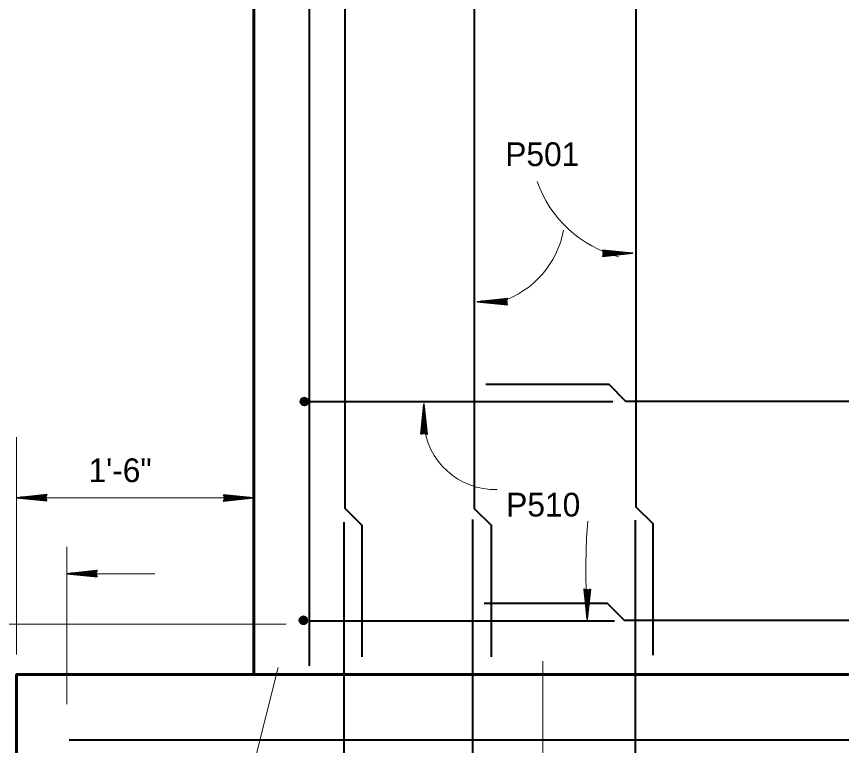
# Model space of a CAD drawing. Extents: x 3.64 to 6.84, y -0.8 to 1.19.
# Drawn here: x 3.9444 to 4.2342, y -0.0837 to 0.1724 of the extents above; entities that cross this region are included whole.
import ezdxf

# ---------------------------------------------------------------- set-up
doc = ezdxf.new("R2010")
doc.units = 0
doc.header["$LTSCALE"] = 0.0033
doc.linetypes.add('DOT_DASHED', pattern=[7.7, 5, -1.2, 0.3, -1.2])
doc.linetypes.add('MEDIUM_DASHED', pattern=[4.5, 3, -1.5])
doc.layers.add('1', color=7, linetype='Continuous', lineweight=40)
doc.layers.add('5', color=7, linetype='MEDIUM_DASHED', lineweight=13)

msp = doc.modelspace()

# ---------------------------------------------------------------- linework, layer by layer
at = {"layer": '1'}
for p, q in [((4.04725, 0.2535), (4.04725, -0.055667)), ((4.044333, 0.036417), (4.044417, 0.037917)), ((4.0445, 0.036417), (4.044583, 0.037917)), ((4.044583, 0.036417), (4.044667, 0.037917)), ((4.046583, 0.0375), (4.044583, 0.037833)), ((4.046667, 0.03775), (4.044667, 0.038083)), ((4.046583, 0.037667), (4.044667, 0.038)), ((4.044667, 0.036417), (4.04475, 0.037917)), ((4.046583, 0.037583), (4.044667, 0.037917)), ((4.04475, 0.036417), (4.044833, 0.037917)), ((4.044833, 0.036417), (4.044917, 0.037917)), ((4.044917, 0.036417), (4.045, 0.037917)), ((4.045, 0.036417), (4.045083, 0.037917)), ((4.045, 0.036417), (4.045083, 0.037917)), ((4.045083, 0.036417), (4.04525, 0.037917)), ((4.04525, 0.036417), (4.045417, 0.037917)), ((4.045417, 0.036333), (4.0455, 0.037833)), ((4.0455, 0.036333), (4.045583, 0.037833)), ((4.045583, 0.036333), (4.045667, 0.037833)), ((4.045667, 0.036333), (4.04575, 0.037833)), ((4.04575, 0.036333), (4.045833, 0.037833)), ((4.045833, 0.036333), (4.045917, 0.037833)), ((4.045917, 0.036333), (4.046, 0.037833)), ((4.046083, 0.036333), (4.046167, 0.037833)), ((4.046167, 0.036333), (4.04625, 0.037833)), ((4.04625, 0.036333), (4.046333, 0.037833)), ((4.046333, 0.036333), (4.046417, 0.037833)), ((4.046417, 0.036333), (4.0465, 0.037833)), ((4.046417, 0.036583), (4.044417, 0.037)), ((4.046417, 0.0365), (4.044417, 0.036917)), ((4.046417, 0.036417), (4.044417, 0.03675)), ((4.046417, 0.036333), (4.044417, 0.036667)), ((4.046333, 0.036167), (4.044417, 0.0365)), ((4.0465, 0.036917), (4.0445, 0.037333)), ((4.0465, 0.036833), (4.0445, 0.037167)), ((4.046417, 0.03675), (4.0445, 0.037083)), ((4.046583, 0.03725), (4.044583, 0.037667)), ((4.0465, 0.037083), (4.044583, 0.0375)), ((4.0465, 0.037), (4.044583, 0.037417)), ((4.046583, 0.037167), (4.153917, 0.037167)), ((4.059417, -0.00525), (4.059417, -0.117083)), ((4.104583, -0.00425), (4.104583, -0.11725)), ((4.161667, -0.0045), (4.161667, -0.1175)), ((4.044, -0.040417), (4.044083, -0.038917)), ((4.046083, -0.04025), (4.044083, -0.039833)), ((4.046083, -0.040333), (4.044083, -0.039917)), ((4.046083, -0.040417), (4.044083, -0.040083)), ((4.046083, -0.0405), (4.044083, -0.040167)), ((4.046, -0.040667), (4.044083, -0.040333)), ((4.044167, -0.040417), (4.04425, -0.038917)), ((4.046167, -0.039917), (4.044167, -0.0395)), ((4.046167, -0.04), (4.044167, -0.039667)), ((4.046083, -0.040083), (4.044167, -0.03975)), ((4.04425, -0.040417), (4.044333, -0.038917)), ((4.04625, -0.039333), (4.04425, -0.039)), ((4.04625, -0.039583), (4.04425, -0.039167)), ((4.046167, -0.03975), (4.04425, -0.039333)), ((4.046167, -0.039833), (4.04425, -0.039417)), ((4.046333, -0.039083), (4.044333, -0.03875)), ((4.04625, -0.039167), (4.044333, -0.038833)), ((4.044333, -0.040417), (4.044417, -0.038917)), ((4.04625, -0.03925), (4.044333, -0.038917)), ((4.044417, -0.040417), (4.0445, -0.038917)), ((4.0445, -0.040417), (4.044583, -0.038917)), ((4.044583, -0.040417), (4.044667, -0.038917)), ((4.044667, -0.040417), (4.04475, -0.038917)), ((4.044667, -0.040417), (4.04475, -0.038917)), ((4.04475, -0.040417), (4.044917, -0.038917)), ((4.044917, -0.040417), (4.045083, -0.038917)), ((4.045083, -0.0405), (4.045167, -0.039)), ((4.045167, -0.0405), (4.04525, -0.039)), ((4.04525, -0.0405), (4.045333, -0.039)), ((4.045333, -0.0405), (4.045417, -0.039)), ((4.045417, -0.0405), (4.0455, -0.039)), ((4.0455, -0.0405), (4.045583, -0.039)), ((4.045583, -0.0405), (4.045667, -0.039)), ((4.04575, -0.0405), (4.045833, -0.039)), ((4.045833, -0.0405), (4.045917, -0.039)), ((4.045917, -0.0405), (4.046, -0.039)), ((4.046, -0.0405), (4.046083, -0.039)), ((4.046083, -0.0405), (4.046167, -0.039)), ((4.047667, -0.039833), (4.1545, -0.039833))]:
    msp.add_line(p, q, dxfattribs=at)
at = {"layer": '1', "lineweight": 35}
for p, q in [((4.1505, 0.09025), (4.158333, 0.089333)), ((4.1505, 0.09025), (4.158333, 0.089333)), ((4.1505, 0.090167), (4.158333, 0.089333)), ((4.1505, 0.090083), (4.158333, 0.08925)), ((4.1505, 0.090083), (4.158333, 0.089083)), ((4.15025, 0.08925), (4.160833, 0.08925)), ((4.150417, 0.088583), (4.15775, 0.089333)), ((4.1505, 0.088417), (4.157833, 0.08925)), ((4.1505, 0.088333), (4.157833, 0.089083)), ((4.1505, 0.088167), (4.157833, 0.089)), ((4.116583, 0.07325), (4.10925, 0.072417)), ((4.116583, 0.073083), (4.10925, 0.072333)), ((4.116583, 0.073), (4.10925, 0.072167)), ((4.116667, 0.072833), (4.109333, 0.072083)), ((4.116833, 0.072167), (4.10625, 0.072167)), ((4.116583, 0.071333), (4.10875, 0.072333)), ((4.116583, 0.071333), (4.10875, 0.072167)), ((4.116583, 0.071167), (4.10875, 0.072083)), ((4.116583, 0.071167), (4.10875, 0.072083)), ((4.116583, 0.07125), (4.10875, 0.072083)), ((4.0875, 0.025667), (4.0875, 0.03625)), ((4.0865, 0.025917), (4.087417, 0.03375)), ((4.0865, 0.025917), (4.087417, 0.03375)), ((4.086583, 0.025917), (4.087417, 0.03375)), ((4.086667, 0.025917), (4.0875, 0.03375)), ((4.086667, 0.025917), (4.087667, 0.03375)), ((4.088167, 0.025833), (4.087417, 0.033167)), ((4.088333, 0.025917), (4.0875, 0.03325)), ((4.088417, 0.025917), (4.087667, 0.03325)), ((4.088583, 0.025917), (4.08775, 0.03325)), ((3.955, 0.003333), (3.944417, 0.003333)), ((3.95475, 0.0025), (3.946917, 0.0035)), ((3.95475, 0.0025), (3.946917, 0.003333)), ((3.95475, 0.002333), (3.946917, 0.00325)), ((3.95475, 0.002333), (3.946917, 0.00325)), ((3.95475, 0.002417), (3.946917, 0.00325)), ((3.95475, 0.004417), (3.947417, 0.003583)), ((3.95475, 0.00425), (3.947417, 0.0035)), ((3.95475, 0.004167), (3.947417, 0.003333)), ((3.954833, 0.004), (3.9475, 0.00325)), ((4.017083, 0.003333), (4.027667, 0.003333)), ((4.01725, 0.002667), (4.024583, 0.003417)), ((4.017333, 0.004333), (4.025167, 0.003417)), ((4.017333, 0.004333), (4.025167, 0.003417)), ((4.017333, 0.00425), (4.025167, 0.003417)), ((4.017333, 0.004167), (4.025167, 0.003333)), ((4.017333, 0.004167), (4.025167, 0.003167)), ((4.017333, 0.0025), (4.024667, 0.003333)), ((4.017333, 0.002417), (4.024667, 0.003167)), ((4.017333, 0.00225), (4.024667, 0.003083)), ((3.972417, -0.024167), (3.964583, -0.023167)), ((3.972417, -0.02225), (3.965083, -0.023083)), ((3.972417, -0.022417), (3.965083, -0.023167)), ((3.972417, -0.0225), (3.965083, -0.023333)), ((3.9725, -0.022667), (3.965167, -0.023417)), ((3.972667, -0.023333), (3.962083, -0.023333)), ((3.972417, -0.024167), (3.964583, -0.023333)), ((3.972417, -0.024333), (3.964583, -0.023417)), ((3.972417, -0.024333), (3.964583, -0.023417)), ((3.972417, -0.02425), (3.964583, -0.023417)), ((4.14425, -0.028917), (4.145, -0.03625)), ((4.144917, -0.02875), (4.144917, -0.039333)), ((4.143833, -0.029), (4.144667, -0.036333)), ((4.144, -0.029), (4.14475, -0.036333)), ((4.144083, -0.029), (4.144917, -0.036333)), ((4.14575, -0.029), (4.14475, -0.036833)), ((4.14575, -0.029), (4.144917, -0.036833)), ((4.145917, -0.029), (4.145, -0.036833)), ((4.145917, -0.029), (4.145, -0.036833)), ((4.145833, -0.029), (4.145, -0.036833))]:
    msp.add_line(p, q, dxfattribs=at)
at = {"layer": '1', "lineweight": 13}
for p, q in [((3.944417, -0.05175), (3.944417, 0.024583)), ((3.944333, 0.003333), (4.02725, 0.003333)), ((3.962083, -0.069167), (3.962083, -0.013917)), ((3.972083, -0.023333), (3.992917, -0.023333)), ((4.039167, -0.041083), (3.863583, -0.041083))]:
    msp.add_line(p, q, dxfattribs=at)
at = {"layer": '1', "lineweight": 60}
for points in [[(3.944417, -0.142083), (3.944417, -0.05875), (4.02775, -0.05875), (4.02775, 0.274583)], [(4.02775, -0.05875), (4.270917, -0.05875), (4.611083, -0.05875)]]:
    msp.add_lwpolyline(points, dxfattribs=at)
at = {"layer": '1'}
for points in [[(4.05975, 0.253583), (4.05975, -0.000333), (4.065667, -0.00625), (4.065667, -0.0525)], [(4.111083, 0.253167), (4.111083, 0.213833), (4.105167, 0.207917), (4.105167, -0.000417), (4.111083, -0.006333), (4.111083, -0.052583)], [(4.167917, 0.252), (4.167917, 0.214417), (4.162, 0.2085), (4.162, 0.000167), (4.167917, -0.00575), (4.167917, -0.052)], [(4.51775, 0.043083), (4.474083, 0.043083), (4.468167, 0.037167), (4.253417, 0.037167), (4.1585, 0.037167), (4.152583, 0.043083), (4.10925, 0.043083)], [(4.046833, 0.037167), (4.04425, 0.036833), (4.046583, 0.036333), (4.04425, 0.037417), (4.046667, 0.037833), (4.044667, 0.038167), (4.044667, 0.036083), (4.045583, 0.038417), (4.045333, 0.035833), (4.046333, 0.038167), (4.046, 0.035833), (4.045167, 0.038417), (4.04675, 0.036667), (4.044333, 0.0365), (4.046, 0.038333), (4.044917, 0.035917), (4.046583, 0.036333), (4.046667, 0.037833), (4.045583, 0.038417), (4.044667, 0.038167), (4.04425, 0.037417), (4.044333, 0.0365), (4.044917, 0.035917), (4.045583, 0.037), (4.044417, 0.037917), (4.046333, 0.038167), (4.045583, 0.037), (4.046667, 0.0365), (4.045667, 0.035833), (4.045583, 0.036917), (4.04475, 0.038167), (4.04675, 0.036917), (4.045417, 0.036583), (4.044667, 0.036083)], [(4.517167, -0.033833), (4.4735, -0.033833), (4.467583, -0.03975), (4.252833, -0.03975), (4.157917, -0.03975), (4.152, -0.033833), (4.108667, -0.033833)], [(4.0465, -0.039667), (4.043917, -0.04), (4.04625, -0.0405), (4.043917, -0.039417), (4.046333, -0.039), (4.044333, -0.038667), (4.044333, -0.04075), (4.04525, -0.038417), (4.045, -0.041), (4.046, -0.038667), (4.045667, -0.041), (4.044833, -0.038417), (4.046417, -0.040167), (4.044, -0.040333), (4.045667, -0.0385), (4.044583, -0.040917), (4.04625, -0.0405), (4.046333, -0.039), (4.04525, -0.038417), (4.044333, -0.038667), (4.043917, -0.039417), (4.044, -0.040333), (4.044583, -0.040917), (4.04525, -0.039833), (4.044083, -0.038917), (4.046, -0.038667), (4.04525, -0.039833), (4.046333, -0.040333), (4.045333, -0.041), (4.04525, -0.039917), (4.044417, -0.038667), (4.046417, -0.039917), (4.045083, -0.04025), (4.044333, -0.04075)], [(3.962833, -0.081667), (4.270917, -0.081667), (4.332667, -0.081667)]]:
    msp.add_lwpolyline(points, dxfattribs=at)
at = {"layer": '1', "lineweight": 35}
for points in [[(4.15025, 0.090333), (4.160833, 0.08925), (4.15025, 0.088083), (4.150833, 0.08925)], [(4.151, 0.089333), (4.155667, 0.089417), (4.155667, 0.089333), (4.15475, 0.089333), (4.151, 0.089417), (4.154, 0.0895), (4.150833, 0.089583), (4.153083, 0.089667), (4.150833, 0.08975), (4.154333, 0.0895), (4.159, 0.089333), (4.158083, 0.089083), (4.159333, 0.089083), (4.151, 0.089083), (4.153417, 0.088917), (4.150833, 0.088917), (4.156167, 0.089333), (4.150833, 0.088667)], [(4.116833, 0.071083), (4.10625, 0.072167), (4.116833, 0.073333), (4.11625, 0.072167)], [(4.116083, 0.072083), (4.111417, 0.072), (4.111417, 0.072083), (4.112333, 0.072083), (4.116083, 0.072), (4.113083, 0.071917), (4.11625, 0.071833), (4.114, 0.07175), (4.11625, 0.071667), (4.11275, 0.071917), (4.108083, 0.072083), (4.109, 0.072333), (4.10775, 0.072333), (4.116083, 0.072333), (4.113667, 0.0725), (4.11625, 0.0725), (4.110917, 0.072083), (4.11625, 0.07275)], [(4.086417, 0.025667), (4.0875, 0.03625), (4.088667, 0.025667), (4.0875, 0.02625)], [(4.087417, 0.026417), (4.087333, 0.031083), (4.087417, 0.031083), (4.087417, 0.030167), (4.087333, 0.026417), (4.08725, 0.029417), (4.087167, 0.02625), (4.087083, 0.0285), (4.087, 0.02625), (4.08725, 0.02975), (4.087417, 0.034417), (4.087667, 0.0335), (4.087667, 0.03475), (4.087667, 0.026417), (4.087833, 0.028833), (4.087833, 0.02625), (4.087417, 0.031583), (4.088083, 0.02625)], [(3.955, 0.00225), (3.944417, 0.003333), (3.955, 0.0045), (3.954417, 0.003333)], [(3.95425, 0.00325), (3.949583, 0.003167), (3.949583, 0.00325), (3.9505, 0.00325), (3.95425, 0.003167), (3.95125, 0.003083), (3.954417, 0.003), (3.952167, 0.002917), (3.954417, 0.002833), (3.950917, 0.003083), (3.94625, 0.00325), (3.947167, 0.0035), (3.945917, 0.0035), (3.95425, 0.0035), (3.951833, 0.003667), (3.954417, 0.003667), (3.949083, 0.00325), (3.954417, 0.003917)], [(4.017083, 0.004417), (4.027667, 0.003333), (4.017083, 0.002167), (4.017667, 0.003333)], [(4.017833, 0.003417), (4.0225, 0.0035), (4.0225, 0.003417), (4.021583, 0.003417), (4.017833, 0.0035), (4.020833, 0.003583), (4.017667, 0.003667), (4.019917, 0.00375), (4.017667, 0.003833), (4.021167, 0.003583), (4.025833, 0.003417), (4.024917, 0.003167), (4.026167, 0.003167), (4.017833, 0.003167), (4.02025, 0.003), (4.017667, 0.003), (4.023, 0.003417), (4.017667, 0.00275)], [(3.972667, -0.024417), (3.962083, -0.023333), (3.972667, -0.022167), (3.972083, -0.023333)], [(3.971917, -0.023417), (3.96725, -0.0235), (3.96725, -0.023417), (3.968167, -0.023417), (3.971917, -0.0235), (3.968917, -0.023583), (3.972083, -0.023667), (3.969833, -0.02375), (3.972083, -0.023833), (3.968583, -0.023583), (3.963917, -0.023417), (3.964833, -0.023167), (3.963583, -0.023167), (3.971917, -0.023167), (3.9695, -0.023), (3.972083, -0.023), (3.96675, -0.023417), (3.972083, -0.02275)], [(4.146, -0.02875), (4.144917, -0.039333), (4.14375, -0.02875), (4.144917, -0.029333)], [(4.145, -0.0295), (4.145083, -0.034167), (4.145, -0.034167), (4.145, -0.03325), (4.145083, -0.0295), (4.145167, -0.0325), (4.14525, -0.029333), (4.145333, -0.031583), (4.145417, -0.029333), (4.145167, -0.032833), (4.145, -0.0375), (4.14475, -0.036583), (4.14475, -0.037833), (4.14475, -0.0295), (4.144583, -0.031917), (4.144583, -0.029333), (4.145, -0.034667), (4.144333, -0.029333)]]:
    msp.add_lwpolyline(points, close=True, dxfattribs=at)
for points in [[(4.151, 0.089333), (4.150583, 0.090083), (4.150833, 0.089833), (4.151, 0.0895), (4.15125, 0.089583), (4.151083, 0.089917), (4.150917, 0.089167), (4.15075, 0.088667), (4.1505, 0.08825)], [(4.116083, 0.072083), (4.1165, 0.071333), (4.11625, 0.071583), (4.116083, 0.071917), (4.115833, 0.071833), (4.116, 0.0715), (4.116167, 0.07225), (4.116333, 0.07275), (4.116583, 0.073167)], [(4.087417, 0.026417), (4.086667, 0.026), (4.086917, 0.02625), (4.08725, 0.026417), (4.087167, 0.026667), (4.086833, 0.0265), (4.087583, 0.026333), (4.088083, 0.026167), (4.0885, 0.025917)], [(3.95425, 0.00325), (3.954667, 0.0025), (3.954417, 0.00275), (3.95425, 0.003083), (3.954, 0.003), (3.954167, 0.002667), (3.954333, 0.003417), (3.9545, 0.003917), (3.95475, 0.004333)], [(4.017833, 0.003417), (4.017417, 0.004167), (4.017667, 0.003917), (4.017833, 0.003583), (4.018083, 0.003667), (4.017917, 0.004), (4.01775, 0.00325), (4.017583, 0.00275), (4.017333, 0.002333)], [(3.971917, -0.023417), (3.972333, -0.024167), (3.972083, -0.023917), (3.971917, -0.023583), (3.971667, -0.023667), (3.971833, -0.024), (3.972, -0.02325), (3.972167, -0.02275), (3.972417, -0.022333)], [(4.145, -0.0295), (4.14575, -0.029083), (4.1455, -0.029333), (4.145167, -0.0295), (4.14525, -0.02975), (4.145583, -0.029583), (4.144833, -0.029417), (4.144333, -0.02925), (4.143917, -0.029)]]:
    msp.add_lwpolyline(points, dxfattribs=at)
at = {"layer": '1'}
for centre in [(4.0455, 0.037117), (4.045167, -0.039717)]:
    msp.add_circle(centre, 0.00132, dxfattribs=at)
at = {"layer": '1', "lineweight": 13}
for centre, radius, start, end in [((4.166514, 0.128263), 0.041634, 199.42455, 255.25359), ((4.104194, 0.103465), 0.032964, 288.49999, 349.28048), ((4.112445, 0.031231), 0.024994, 183.58816, 271.84601), ((4.355649, -0.022042), 0.211261, 175.35045, 181.86489)]:
    msp.add_arc(centre, radius, start, end, dxfattribs=at)
at = {"layer": '5', "linetype": 'DOT_DASHED'}
for points in [[(4.12925, -0.054), (4.12925, -0.137667), (4.12925, -0.260083)], [(4.03625, -0.056333), (4.015667, -0.1385), (3.986333, -0.25625)]]:
    msp.add_lwpolyline(points, dxfattribs=at)

# ---------------------------------------------------------------- texts
at = {"layer": '1'}
for s, p in [('P501', (4.116083, 0.119833)), ('1\'-6"', (3.969667, 0.008833)), ('P510', (4.116417, -0.00325))]:
    msp.add_text(s, height=0.008334, dxfattribs=at).set_placement(p)

doc.saveas('drawing.dxf')
